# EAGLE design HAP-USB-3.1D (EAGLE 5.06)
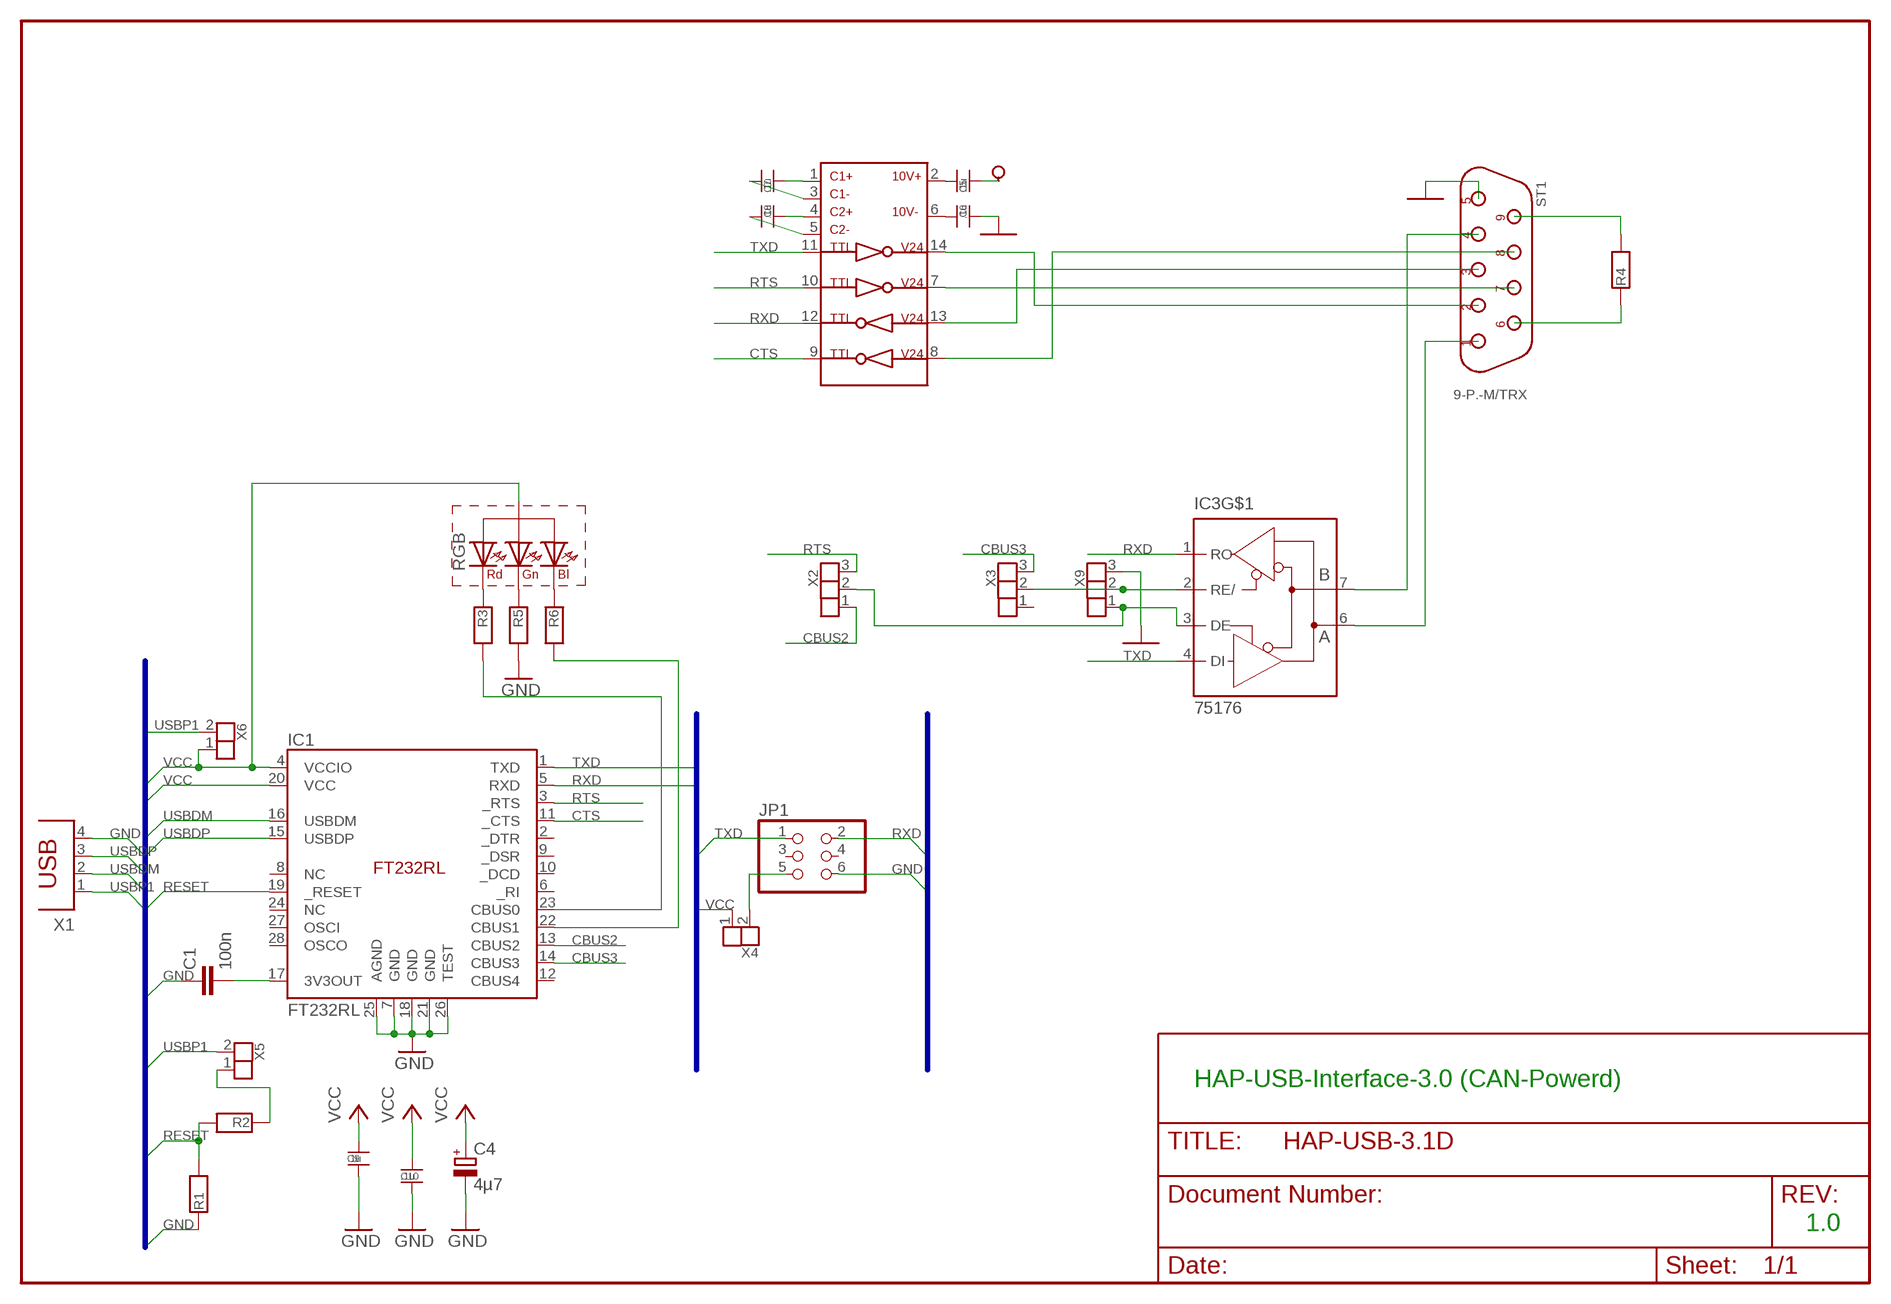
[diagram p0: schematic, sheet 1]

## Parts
C1  100n  C-EUC0805  [C0805]
C4  4µ7  CPOL-EUE2,5-6E  [E2,5-6E]
C5  .1u  C0805  [0805]
C6  .1u  C0805  [0805]
C7  .1u  C0805  [0805]
C8  .1u  C0805  [0805]
C9  .1u  C0805  [0805]
C10  .1u  C0805  [0805]
IC1  FT232RL  [SSOP-28]
IC2  MAX232SO16  MAX232SO  [SO16]
IC3  75176  [SO8]
JP1  PINHD-2X3  [2X03]
R1  R0805  [0805]
R2  R0805  [0805]
R3  R0805  [0805]
R4  R0805  [0805]
R5  R0805  [0805]
R6  R0805  [0805]
RGB  RGB  RGBEVER  [DTEVER]
ST1  9-P.-M/TRX  DB9M-PL  [DB9M-PL]
X1  PN61729  [PN61729]
X2  3-P-SMD  [3-P-SMD]
X3  3-P-SMD  [3-P-SMD]
X4  2-P-SMDOFFEN  [2-P-SMD]
X5  2-P-SMDOFFEN  [2-P-SMD]
X6  2-P-SMDOFFEN  [2-P-SMD]
X9  3-P-SMD  [3-P-SMD]

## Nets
CBUS2: IC1.13(CBUS2) X2.1
CBUS3: IC1.14(CBUS3) X3.3
CTS: IC1.11(_CTS) IC2.9
GND: C1.1 C4.- C6.1 C9.2 C10.2 IC1.7(GND) IC1.18(GND) IC1.21(GND) IC1.25(AGND) IC1.26(TEST) JP1.6 R1.1 R5.2 ST1.5 X1.4 X9.3
N$1: C7.2 IC2.1
N$2: C1.2 IC1.17(3V3OUT)
N$3: C8.1 IC2.4
N$4: C5.1 IC2.2
N$5: C6.2 IC2.6
N$6: C8.2 IC2.5
N$7: C7.1 IC2.3
N$8: IC2.13 ST1.3
N$9: IC2.8 ST1.8
N$10: IC2.14 ST1.2
N$11: IC2.7 ST1.7
N$12: R4.2 ST1.9
N$13: R4.1 ST1.6
N$14: IC3.6(A) ST1.1
N$15: IC3.7(B) ST1.4
N$16: IC3.2(RE/) X3.2 X9.2
N$17: IC3.3(DE) X2.2 X9.1
N$18: R2.1 X5.1
N$19: JP1.5 X4.2
N$20: R3.1 RGB.1(R)
N$21: R5.1 RGB.2(G)
N$22: R6.1 RGB.3(B)
N$23: IC1.23(CBUS0) R3.2
N$24: IC1.22(CBUS1) R6.2
RESET: IC1.19(_RESET) R1.2 R2.2
RTS: IC1.3(_RTS) IC2.10 X2.3
RXD: IC1.5(RXD) IC2.12 IC3.1(RO) JP1.2
TXD: IC1.1(TXD) IC2.11 IC3.4(DI) JP1.1
USBDM: IC1.16(USBDM) X1.2
USBDP: IC1.15(USBDP) X1.3
USBP1: X1.1 X5.2 X6.2
VCC: C4.+ C5.2 C9.1 C10.1 IC1.4(VCCIO) IC1.20(VCC) RGB.4(A) X4.1 X6.1
Unconnected: IC1.2(_DTR) IC1.6(_RI) IC1.8(NC) IC1.9(_DSR) IC1.10(_DCD) IC1.12(CBUS4) IC1.24(NC) IC1.27(OSCI) IC1.28(OSCO) JP1.3 JP1.4 X3.1

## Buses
VCC,GND,TXD,RXD,USBDM,USBDP,RESET,USBP1

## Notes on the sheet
- HAP-USB-Interface-3.0 (CAN-Powerd)
- 1.0

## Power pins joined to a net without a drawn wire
GND: IC2.15(GND) IC3.5(GND)
VCC: IC2.16(VCC) IC3.8(VCC)

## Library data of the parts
C1 = rcl:C-EU: CAPACITOR, European symbol
C4 = rcl:CPOL-EU: POLARIZED CAPACITOR, European symbol
C5-C10 = OWN:C0805
IC1 = ftdi4:FT232RL
IC2 = OWN:MAX232
IC3 = OWN:75176
JP1 = pinhead:PINHD-2X3: PIN HEADER
R1-R6 = OWN:R0805
RGB = OWN:RGBEVER
ST1 = OWN:DB9M-PL
X1 = con-berg:PN61729: BERG USB connector
X2 X3 X9 = OWN:3-P-SMD
X4-X6 = OWN:2-P-SMD

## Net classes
0 default: width 0.18 mm, drill 0.4 mm, clearance 0.18 mm

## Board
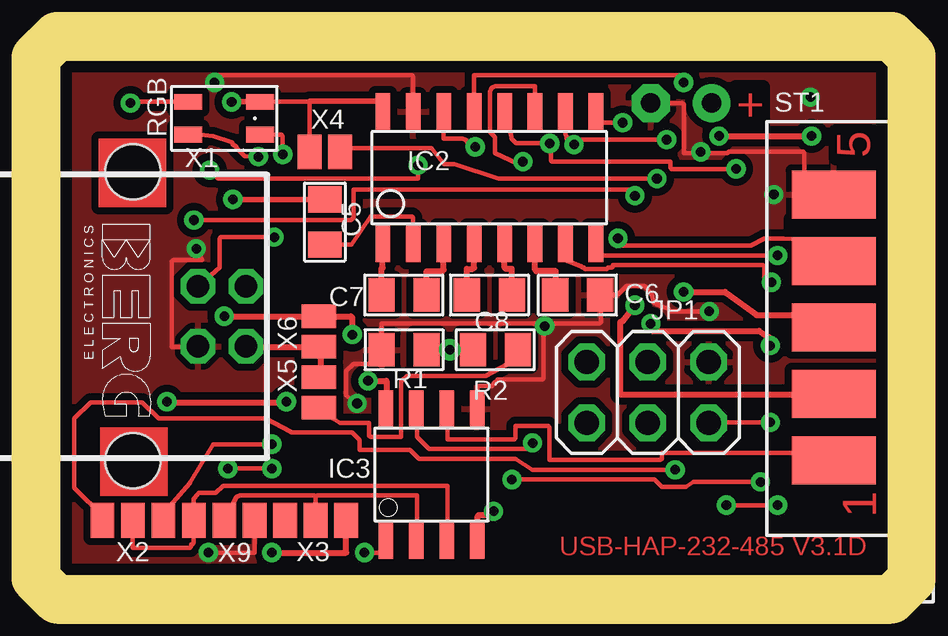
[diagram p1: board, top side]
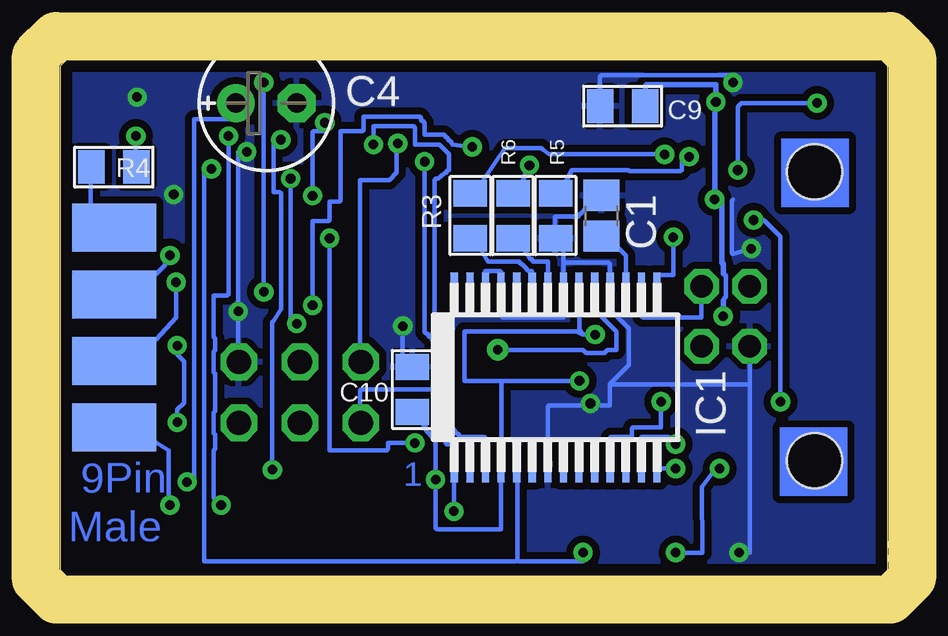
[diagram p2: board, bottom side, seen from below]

Size 34.5 x 21.5 mm. Coordinates in mm from the lower left corner, seen from the top.
Outline: 0.25,0 0,0.25 0,21.25 0.25,21.5 34.25,21.5 34.5,21.25 34.5,0.25 34.25,0 0.25,0
Copper layers (1*16): Top 0.035mm / dielectric 1.5mm / Bottom 0.035mm
Design rules "default *": minimum track width 0.15mm, minimum drill 0.3mm, track to track 0.15mm, track to pad 0.15mm, pad to pad 0.15mm, via to via 0.15mm, smd to smd 0mil, copper to edge 0.5mm, drill to drill 8mil, minimum pad ring 0.2mm, minimum via ring 0.2mm, stop-mask expansion 4mil, vias tented up to drill 0mil, thermal gap 10mil
tRestrict: area 30.5,14.2 to 33.9,14.9
bRestrict: area 16.4,11.2 to 16.5,12.6
Milling: 10 lines

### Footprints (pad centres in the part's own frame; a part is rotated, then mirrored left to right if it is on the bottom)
C0805 = smd 1.3 x 1.5: 1 -0.85,0; 2 0.85,0
E2,5-6E = drill 0.813 pad 1.575 round: + -1.27,0 | drill 0.813 pad 1.575 octagon: - 1.27,0
0805 = smd 1.092 x 1.397: 1 -0.94,0; 2 0.94,0
SSOP-28 = smd 0.3 x 1.5: 1 -4.225,-3.625; 2 -3.575,-3.625; 3 -2.925,-3.625; 4 -2.275,-3.625; 5 -1.625,-3.625; 6 -0.975,-3.625; 7 -0.325,-3.625; 8 0.325,-3.625; 9 0.975,-3.625; 10 1.625,-3.625; 11 2.275,-3.625; 12 2.925,-3.625; 13 3.575,-3.625; 14 4.225,-3.625; 15 4.225,3.625; 16 3.575,3.625; 17 2.925,3.625; 18 2.275,3.625; 19 1.625,3.625; 20 0.975,3.625; 21 0.325,3.625; 22 -0.325,3.625; 23 -0.975,3.625; 24 -1.625,3.625; 25 -2.275,3.625; 26 -2.925,3.625; 27 -3.575,3.625; 28 -4.225,3.625
SO16 = smd 0.61 x 1.524: 1 -4.445,-2.819; 2 -3.175,-2.819; 3 -1.905,-2.819; 4 -0.635,-2.819; 5 0.635,-2.819; 6 1.905,-2.819; 7 3.175,-2.819; 8 4.445,-2.819; 9 4.445,2.692; 10 3.175,2.692; 11 1.905,2.692; 12 0.635,2.692; 13 -0.635,2.692; 14 -1.905,2.692; 15 -3.175,2.692; 16 -4.445,2.692
SO8 = smd 0.61 x 1.524: 1 -1.905,-2.743; 2 -0.635,-2.743; 3 0.635,-2.743; 4 1.905,-2.743; 5 1.905,2.743; 6 0.635,2.743; 7 -0.635,2.743; 8 -1.905,2.743
2X03 = drill 1.016 octagon: 1 -2.54,-1.27; 2 -2.54,1.27; 3 0,-1.27; 4 0,1.27; 5 2.54,-1.27; 6 2.54,1.27
DTEVER = smd 0.66 x 1.168: 1 -0.686,-1.499; 2 -0.686,1.499; 3 0.686,1.499; 4 0.686,-1.499
DB9M-PL = smd 2 x 3.5: 1 0.334,0; 2 3.108,0; 3 5.882,0; 4 8.656,0; 5 11.43,0 | smd 2 x 3.5 bottom: 6 1.721,0; 7 4.495,0; 8 7.269,0; 9 10.043,0
PN61729 = drill 0.95 octagon: 1 1.25,4.71; 2 -1.25,4.71; 3 -1.25,2.71; 4 1.25,2.71 | hole 2.3: -6.02,0; 6.02,0
3-P-SMD = smd 0.991 x 1.448: 1 0,0; 2 1.27,0; 3 2.54,0
2-P-SMD = smd 0.991 x 1.448: 1 0,0; 2 1.27,0

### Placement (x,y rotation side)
C1  11.93,15 270 bottom
C4  25.9,19.7 0 bottom
C5  11.04,14.75 90 top
C6  21.58,11.7 180 top
C7  14.34,11.7 180 top
C8  17.9,11.7 0 top
C9  11.04,19.57 180 bottom
C10  19.8,7.76 90 bottom
IC1  13.84,8.27 0 bottom
IC2  17.9,16.65 0 top
IC3  15.49,4.21 0 top
JP1  24.5,7.64 0 top
R1  14.34,9.41 0 top
R2  18.15,9.41 180 top
R3  17.39,15 270 bottom
R4  32.25,17.03 180 bottom
R5  13.84,15 270 bottom
R6  15.61,15 270 bottom
RGB  6.85,19.06 90 top
ST1  32.25,4.46 90 top
X1  3.04,10.81 270 top
X2  4.31,2.3 180 top
X3  9.39,2.3 0 top
X4  10.41,17.67 0 top
X5  10.79,7 90 top
X6  10.79,10.81 270 top
X9  5.58,2.3 0 top

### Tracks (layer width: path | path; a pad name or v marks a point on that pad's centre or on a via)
CBUS2  (via drill 0.4)
  Top 0.18: v8.83,5.48 6.39,5.48 5.43,3.88 5.4,3.85 4.31,2.58 X2.1
  Bottom 0.18: v8.83,5.48 9.09,5.48 9.09,5.73 9.14,5.78 10.25,5.78 10.25,4.66 IC1.13
CBUS3  (via drill 0.4)
  Top 0.18: v7,4.46 v8.83,4.46
  Top 0.254: v8.83,0.95 11.93,0.95 X3.3
  Bottom 0.18: v8.83,0.95 7.71,0.95 7.74,3.7 7.16,4.46 v7,4.46 | v8.83,4.46 9.59,4.46 9.59,4.61 IC1.14
CTS  (via drill 0.4)
  Top 0.18: 9.49,7.23 v9.44,7.25 | 4.56,7.23 4.46,7 v4.46,7.25 | v5.58,14.82 12.13,14.82 12.23,14.92 12.23,16.09 23.97,16.09 v23.97,15.84 | v23.46,18.89 22.34,18.89 IC2.9
  Top 0.254: 4.56,7.23 9.49,7.23
  Bottom 0.18: v9.44,7.25 9.44,6.19 10.61,6.19 10.66,6.14 10.66,5.78 11.52,5.78 11.57,5.73 11.57,4.66 IC1.11 | v4.46,7.25 4.46,14.14 5.15,14.82 v5.58,14.82 | v23.97,15.84 23.97,18.48 23.92,18.53 23.46,18.53 v23.46,18.89
GND  (via drill 0.4)
  Top 0.18: v6.44,20.56 6.44,20.87 14.67,20.87 14.72,20.82 IC2.15 | v6.19,0.95 8.12,0.95 X9.3 | v5.68,13.63 5.94,13.15 4.72,13.15 4.67,13.1 4.67,9.54 5.73,9.54 X1.4 | C4.- 25.95,19.7 26,19.65 26,17.62 26.71,17.62 | 26.71,17.62 27.83,17.62 27.88,17.67 30.98,17.67 31.03,17.62 31.03,15.89 ST1.5 | 20.21,10.5 22.5,10.5 22.55,10.56 22.55,11.67 C6.1 22.6,11.72 23.26,11.72 23.61,12.08 24.38,12.08 24.68,11.72 24.73,11.39 24.88,11.32 24.88,11.29 25.39,11.11 25.39,11.06 25.44,11.01 v27.07,11.01 | 20.21,10.5 13.4,10.5 R1.1 13.4,8.83 12.23,8.83 11.93,8.52 11.93,7.51 v12.39,7.18 | 20.21,10.5 v20.21,10.4 20.16,10.35 20.16,8.22 20.11,8.17 18.23,8.17 18.23,8.12 18.18,8.07 18.13,8.07 18.08,8.02 18.08,7.97 18.03,7.91 17.42,7.91 17.42,6.95 IC3.5 | v26.71,17.67 26.71,17.62
  Bottom 0.18: v6.44,20.56 6.44,20.87 11.93,20.87 11.98,20.82 C9.2 | v6.19,0.95 5.73,0.95 5.73,7.97 | 5.73,7.97 5.73,9.54 X1.4 | 6.44,15.69 6.49,15.64 6.49,13.45 6.44,13.4 v5.68,13.63 | IC1.26 16.76,11.93 16.76,12.69 16.15,12.69 16.1,12.64 16.1,11.93 IC1.25 16.1,11.83 16.1,10.81 16.05,10.76 13.51,10.76 13.51,11.83 IC1.21 13.51,11.93 13.51,13.05 | 13.51,13.05 13.51,14.06 R5.2 13.4,14.06 13.86,14.11 13.86,14.98 12.89,14.98 12.89,15.03 12.84,15.08 12.79,15.08 12.74,15.13 12.23,15.84 11.93,15.84 C1.1 | 13.51,13.05 11.62,13.05 11.57,12.99 11.57,11.93 IC1.18 11.57,11.83 11.57,11.09 10.79,10.3 10.79,8.78 11.55,8.02 11.57,7.97 | 12.13,7.1 11.57,7.1 11.57,7.97 | 12.13,7.1 14.11,7.1 14.16,7.05 14.16,4.66 IC1.7 | v20.21,10.4 20.21,8.73 19.8,8.73 C10.2 | JP1.6 27.07,8.93 v27.07,11.01 27.07,17.67 v26.71,17.67 | 12.13,7.1 v12.39,7.18 | 5.73,7.97 11.57,7.97
  other vias: 29.76,15.89 31.28,19.95
  pour Top (isolate 0.3): -0.01,-0.11 34.54,-0.11 34.54,21.48 -0.01,21.48
  pour Bottom (isolate 0.3): -0.01,-0.11 34.54,-0.11 34.54,21.48 -0.01,21.48
N$1
  Top 0.254: C7.2 13.4,12.79 13.45,12.84 IC2.1
N$2
  Bottom 0.18: IC1.17 10.91,11.93 10.91,13.35 11.47,13.91 11.93,14.16 C1.2
N$3
  Top 0.18: 17.21,12.79 17.26,12.84
  Top 0.254: 17.21,12.79 16.96,12.79 C8.1 | 17.26,12.84 IC2.4
N$4
  Top 0.18: C5.1 12.16,13.81 12.95,14.98 14.67,14.98 14.72,14.92 IC2.2
N$5
  Top 0.18: 19.86,12.69 19.8,12.74 | C6.2 20.67,11.72
  Top 0.254: 20.67,11.72 20.67,12.69 19.86,12.69 | 19.8,12.74 IC2.6
N$6
  Top 0.254: C8.2 18.84,12.79 18.59,12.79 18.53,12.84 IC2.5
N$7
  Top 0.18: 15.94,12.69 15.99,12.74
  Top 0.254: 15.94,12.69 15.28,12.69 C7.1 | 15.99,12.74 IC2.3
N$8  (via drill 0.4)
  Top 0.18: IC2.13 17.26,20.87 25.95,20.87 26,20.82 v26,20.56 | 27.73,11.83 27.78,11.78 | 30.62,10.86 30.68,10.83 32.25,10.35 ST1.3
  Top 0.254: v26,11.83 27.73,11.83 | 27.78,11.78 29.05,10.86 30.62,10.86
  Bottom 0.18: v26,20.56 v26,11.83
N$9  (via drill 0.4)
  Top 0.18: v29.91,13.35 22.34,13.35 IC2.8
  Bottom 0.18: v29.91,13.35 30.12,13.35 30.12,12.94 30.93,12.13 31.18,11.78 31.23,11.72 ST1.8
N$10  (via drill 0.4)
  Top 0.18: IC2.14 15.99,18.23 16.81,18.23 16.86,18.18 16.91,18.18 16.96,18.12 16.96,18.07 17.01,18.02 17.37,18.02 v17.32,17.87 | 23.41,10.61 23.46,10.61 | 32.25,7.56 ST1.2
  Top 0.254: 23.46,10.61 v23.97,11.27 | 23.41,10.61 23.36,10.56 23.36,7.56 32.25,7.56
  Bottom 0.18: v17.32,17.87 18.13,17.97 18.18,18.02 18.18,18.07 18.23,18.12 18.28,18.12 18.33,18.18 18.33,18.23 18.38,18.28 18.43,18.28 18.43,18.33 18.48,18.38 19.3,18.38 19.3,18.89 19.35,18.94 19.4,18.94 19.45,18.99 19.45,19.09 19.5,19.14 21.84,19.14 21.84,18.58 21.89,18.53 22.8,18.53 22.8,15.64 22.85,15.58 23.26,15.58 23.26,14.82 23.31,14.77 23.97,14.77 v23.97,11.27
N$11  (via drill 0.4)
  Top 0.18: v29.66,12.23 29.35,12.23 29.35,12.89 29.3,12.94 23.05,12.94 23.05,12.89 23,12.84 22.85,12.84 22.8,12.79 21.89,12.79 21.84,12.84 21.79,12.84 21.73,12.89 21.07,13.15 IC2.7
  Bottom 0.18: v29.66,12.23 29.66,10.76 30.5,9.84 31.18,9.54 31.18,8.98 31.23,8.93 32.25,8.93 ST1.7
N$12
  Bottom 0.18: R4.2 33.22,17.01 33.22,14.57 33.16,14.52 32.25,14.52 ST1.9
N$13  (via drill 0.4)
  Top 0.18: v27.78,2.94 v29.91,2.94
  Top 0.254: v27.48,18.33 v31.34,18.33
  Bottom 0.18: v31.34,18.33 31.34,17.06 R4.1 | v27.48,18.33 27.48,11.72 27.53,11.67 28.08,11.67 28.08,9.95 28.03,9.9 28.03,9.39 28.08,9.34 28.08,8.47 28.03,8.42 28.03,6.85 28.08,6.8 28.08,5.93 28.03,5.88 28.03,5.27 28.08,5.22 28.08,3.24 v27.78,2.94 | v29.91,2.94 29.96,3.19 29.96,5.22 31.44,6.14 31.49,6.19 ST1.6
N$14
  Top 0.18: IC3.6 16.15,6.95 16.15,5.68 18.94,5.68 18.99,5.73 18.99,6.24 20.36,6.24 20.41,6.19 20.41,4.82 25.04,4.82 25.09,4.87 25.09,5.12 31.18,5.12 31.23,5.07 31.23,4.82 32.25,4.82 ST1.1
N$15  (via drill 0.4)
  Top 0.18: v19.7,5.53 19.7,5.32 19.65,5.27 15.38,5.27 14.88,5.78 14.88,6.95 IC3.7 | v23.26,14.06 23.26,13.76 28.8,13.76 29.35,14.06 30.17,14.06 31.23,14.01 31.23,13.1 32.25,13.1 ST1.4
  Bottom 0.18: v19.7,5.53 20.82,5.53 20.82,5.27 20.87,5.22 23.26,5.22 v23.26,14.06
N$16
  Top 0.18: 10.66,3.24 10.61,3.34 7.51,3.34 7.36,3.29 X9.2 | 10.66,3.24 X3.2 | IC3.2 14.88,1.46 14.88,3.34 10.71,3.34 10.66,3.24
N$17
  Top 0.18: X2.2 3.04,1.16 5.43,1.16 5.48,1.21 5.48,1.31 5.53,1.31 5.58,1.36 X9.1 5.58,3.19 5.73,3.39 5.78,3.44 6.49,3.44 6.8,3.75 16.15,3.75 16.15,1.46 IC3.3
N$18
  Top 0.18: R2.1 18.86,8.8 18.64,8.8 17.75,8.32 14.47,8.32 14.22,8.09 14.22,5.78 12.95,5.78 12.89,5.83 12.89,6.37 11.68,6.37 11.37,6.54 11.37,7 X5.1
N$19  (via drill 0.4)
  Top 0.18: X4.2 11.68,17.82 15.49,17.82 16.02,17.16 16.45,17.16 18.28,16.55 v24.88,16.55 | v24.63,10.5 24.68,10.2 | 29.46,10 29.46,9.95 29.56,9.95 | 29.61,9.9 v29.61,9.59 | v29.61,6.39 27.07,6.39 JP1.5
  Top 0.254: 24.68,10.2 29.15,10.2 29.46,10 | 29.56,9.95 29.61,9.9
  Bottom 0.18: v24.88,16.55 24.88,10.3 24.83,10.25 v24.63,10.5 | v29.61,9.59 29.61,9.21 29.33,8.93 29.33,7.2 29.61,6.92 v29.61,6.39
N$20  (via drill 0.4)
  Top 0.18: v9.29,17.57 9.29,18.33 9.24,18.38 RGB.1
  Bottom 0.18: v9.29,17.57 14.11,17.57 14.37,17.77 14.42,17.82 15.94,17.82 17.21,15.94 R3.1
N$21  (via drill 0.4)
  Top 0.18: v8.27,17.47 7.69,17.49 7.36,17.82 7.36,17.87 7.31,17.92 7.26,17.92 7.21,17.97 7.21,18.02 7.16,18.07 6.39,18.33 5.83,18.38 RGB.2
  Bottom 0.18: v8.27,17.47 8.58,17.47 8.58,16.91 8.63,16.86 10.76,16.86 10.81,16.91 13.15,16.91 13.66,15.94 R5.1
N$22  (via drill 0.4)
  Top 0.18: v14.93,17.11 14.93,16.55 6.6,16.55 v6.24,16.91 | v2.94,19.7 3.04,19.7 3.09,19.75 RGB.3
  Bottom 0.18: v14.93,17.11 15.44,15.94 R6.1 | v6.24,16.91 6.24,19.55 6.09,19.7 v2.94,19.7
N$23
  Bottom 0.18: R3.2 17.21,14.06 16.7,13.15 16.65,13.1 15.33,13.1 15.33,13.05 15.28,12.99 15.23,12.99 15.03,12.79 15.03,12.74 14.98,12.69 14.83,12.69 14.83,11.93 IC1.23
N$24
  Bottom 0.18: R6.2 15.44,14.06 14.93,13.25 14.88,13.2 14.83,13.2 14.83,13.15 14.78,13.1 14.16,13.1 14.16,11.93 IC1.22
RESET  (via drill 0.4 pad 0.9)
  Top 0.18: R2.2 17.21,9.34 15.28,9.34 R1.2 v16.25,9.41
  Bottom 0.18: IC1.19 12.21,11.09 11.29,10.17 11.29,9.41 11.68,9.41 11.8,9.29 12.56,9.29 12.69,9.41 v16.25,9.41
RTS  (via drill 0.4)
  Top 0.18: v25.65,4.41 19.7,4.41 18.99,4.87 14.98,4.87 14.6,5.25 12.49,5.25 12.49,5.65 12.18,5.96 9.64,5.96 9.64,5.98 8.58,6.54 4.11,6.54 3.42,7.23 1.29,7.23 0.6,6.54 0.6,3.65 0.65,3.6 1.77,2.5 X2.3 | 21.43,18.18 21.18,18.18 21.12,18.23 21.12,18.33 21.07,18.38 IC2.10 | v25.29,18.18 21.43,18.18 | 21.43,18.18 v21.43,17.97
  Bottom 0.18: v25.65,4.41 25.65,10.56 25.59,10.61 25.29,11.11 25.29,15.94 25.34,15.99 25.59,15.99 25.59,18.12 25.54,18.18 v25.29,18.18 | v21.43,17.97 21.43,18.73 19.75,18.73 19.7,18.68 19.7,17.97 18.69,17.97 18.28,17.57 18.28,16.91 18.33,16.91 18.38,16.86 18.38,16.8 18.43,16.8 18.48,16.75 18.74,16.55 18.84,16.55 18.89,16.5 18.89,10.35 18.84,10.3 18.79,10.3 18.74,10.25 18.74,10.2 18.69,10.15 18.64,10.15 18.59,10.1 18.59,10.05 18.53,10 18.48,10 18.43,9.95 18.43,9.9 18.38,9.84 18.33,9.84 18.28,9.79 18.28,7.25 18.23,7.25 18.18,7.2 18.18,6.14 18.13,6.09 18.08,6.09 18.03,6.03 18.03,5.98 17.98,5.93 17.92,5.93 17.87,5.88 17.87,5.83 17.82,5.78 16.81,5.78 16.76,5.73 16.76,4.66 IC1.3
RXD  (via drill 0.4)
  Top 0.18: v12.69,0.95 13.61,0.95 13.61,1.46 IC3.1 | IC2.12 18.81,18.3 18.81,18.23 19.02,18.02 v20.41,18.02 20.46,17.97 20.46,17.31 20.52,17.26 25.44,17.26 25.44,17.01 25.49,16.96 v28.19,16.96
  Bottom 0.18: 15.44,0.65 15.44,4.61 IC1.5 | 15.44,0.65 15.38,0.6 12.69,0.6 v12.69,0.95 | v20.41,18.02 20.46,18.28 20.46,16.8 20.77,16.5 21.99,16.5 21.99,8.93 JP1.2 | v28.19,16.96 28.44,16.96 28.49,16.91 28.49,0.6 15.49,0.6 15.44,0.65
TXD  (via drill 0.4)
  Top 0.18: 18.08,2.53 v18.08,2.68 | 17.42,2.48 17.47,2.53 | IC3.4 17.42,1.46 | IC2.11 19.8,20.41 18.13,20.41 18.08,20.36 18.03,20.36 17.98,20.31 17.98,20.26 17.92,20.21 17.92,18.48 18.13,18.28 18.13,17.62 19.07,17.19 19.27,17.29 v19.3,17.26
  Top 0.254: 17.47,2.53 18.08,2.53 | 17.42,1.46 17.42,2.48
  Bottom 0.18: v18.08,2.68 18.08,4.61 IC1.1 18.08,4.71 18.08,5.48 18.38,5.48 18.43,5.53 18.43,5.83 18.59,5.98 18.59,7 18.69,7.1 18.69,7.76 | v19.3,17.26 19.3,10.15 19.25,10.1 19.19,10.1 19.14,10.05 19.14,10 19.09,9.95 19.04,9.95 18.99,9.9 18.99,9.84 18.94,9.79 18.89,9.79 18.84,9.74 18.84,9.69 18.79,9.64 18.74,9.64 18.69,9.59 18.69,7.76 | JP1.1 21.99,6.39 21.99,7.71 21.94,7.76 18.69,7.76
USBDM
  Bottom 0.18: IC1.16 10.25,11.88 10.25,10.81 10.2,10.76 7.76,10.76 7.76,12.03 X1.2
USBDP  (via drill 0.4)
  Top 0.18: v8.93,14.11 6.7,14.11 6.65,14.06 6.65,12.84 5.78,12.08 X1.3
  Bottom 0.18: v8.93,14.11 8.93,12.54 9.54,12.54 9.59,12.49 9.59,11.93 IC1.15
USBP1
  Top 0.18: 10.86,8.32 10.15,8.27 X5.2 | 10.86,9.54 X6.2 | X1.1 7.76,9.54
  Top 0.254: 10.86,8.32 10.86,9.54 7.76,9.54
VCC  (via drill 0.4)
  Top 0.18: RGB.4 13.45,19.75 IC2.16 13.45,19.8 10.41,19.8 X4.1 | 13.61,6.95 IC3.8 | v29.2,3.9 26.41,3.9 26.1,3.7 25.09,3.7 24.78,4 v18.84,4
  Top 0.22: v7.16,19.75 RGB.4 | v7.21,15.69 C5.2
  Top 0.254: v12.18,10.05 12.18,10.76 12.13,10.81 X6.1 v6.85,10.81 | 13.61,6.95 13.61,8.12 v12.84,8.12
  Bottom 0.18: 10.05,20.46 10.1,20.41 | 7.21,19.7 v7.16,19.75 | v12.18,10.05 12.69,10.05 | IC1.20 12.84,11.88 12.84,10.3 12.69,10.05 | 12.69,10.05 12.95,10.17 17.64,10.17 17.64,8.12 16.1,8.12 | 12.92,8.12 v12.84,8.12 12.95,8.02 12.92,8.12 | C10.1 19.8,6.85 19.32,6.75 19.25,6.06 18.94,5.73 18.89,5.73 18.84,5.68 v18.84,4 18.84,1.97 18.79,1.92 16.11,1.92 16.11,4.09 | C4.+ 27.17,19.09 27.22,19.04 28.9,19.04 28.9,3.95 28.95,3.9 v29.2,3.9 | 16.1,8.12 12.92,8.12 | 16.1,8.12 16.1,4.71 IC1.4 | 6.9,15.64 7.16,15.64 v7.21,15.69 | 6.85,12.59 6.8,12.54 6.75,12.54 6.75,11.62 6.8,11.57 6.8,11.52 6.85,11.47
  Bottom 0.22: 10.05,20.46 7.16,20.46 v7.16,19.75 | 10.1,20.41 C9.1 | v7.21,15.69 7.21,19.7 | 6.9,15.64 6.9,13.05 6.85,12.99 6.85,12.59 | v6.85,10.81 6.85,11.47 | 19.32,6.75 19.32,6.26 | IC1.4 16.11,4.09
(copper drawn outside any net)
  shapes: Bottom area x2, Top area x2

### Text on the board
Top: + | 5 | 1 | USB-HAP-232-485 V3.1D
Bottom: 9Pin | 1 | Male
tNames: X2 | X9 | X3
